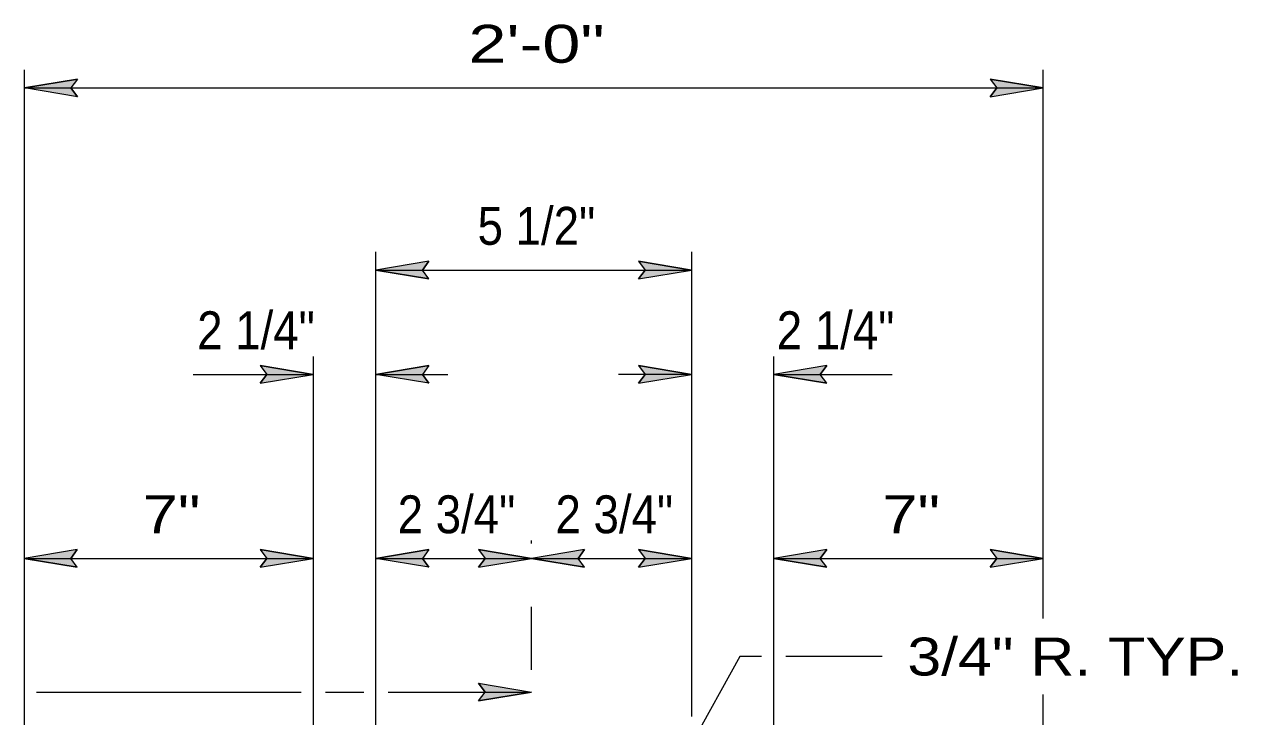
# Model space of a CAD drawing. Extents: x -9.07 to -2.08, y 8.04 to 17.77.
# Drawn here: x -6.811 to -4.889, y 16.67 to 17.766 of the extents above; entities that cross this region are included whole.
import ezdxf
from ezdxf.enums import TextEntityAlignment as Align

# ---------------------------------------------------------------- set-up
doc = ezdxf.new("R2010")
doc.units = 0
doc.header["$LTSCALE"] = 0.024
doc.linetypes.add('DOT_DASHED', pattern=[7.7, 5, -1.2, 0.3, -1.2])
doc.layers.add('10', color=7, linetype='Continuous', lineweight=13)
doc.layers.add('12', color=7, linetype='Continuous', lineweight=53)

msp = doc.modelspace()

# ---------------------------------------------------------------- hatches: boundary and pattern name
at = {"layer": '10'}
for points in [[(-6.81033, 17.665), (-6.72633, 17.679), (-6.73683, 17.665), (-6.72633, 17.651)], [(-5.19733, 17.665), (-5.28133, 17.679), (-5.27083, 17.665), (-5.28133, 17.651)], [(-6.16983, 17.39067), (-6.25383, 17.37667), (-6.16983, 17.36267), (-6.18033, 17.37667)], [(-5.754, 17.37667), (-5.838, 17.39067), (-5.8275, 17.37667), (-5.838, 17.36267)], [(-6.353, 17.2115), (-6.437, 17.2255), (-6.4265, 17.2115), (-6.437, 17.1975)], [(-6.25383, 17.2115), (-6.16983, 17.2255), (-6.18033, 17.2115), (-6.16983, 17.1975)], [(-5.754, 17.2115), (-5.838, 17.2255), (-5.8275, 17.2115), (-5.838, 17.1975)], [(-5.54, 17.2255), (-5.624, 17.2115), (-5.54, 17.1975), (-5.5505, 17.2115)], [(-6.81067, 16.92017), (-6.72667, 16.90617), (-6.73717, 16.92017), (-6.72667, 16.93417)], [(-6.437, 16.90617), (-6.353, 16.92017), (-6.437, 16.93417), (-6.4265, 16.92017)], [(-6.18033, 16.92017), (-6.16983, 16.90617), (-6.25383, 16.92017), (-6.16983, 16.93417)], [(-6.09133, 16.93417), (-6.08083, 16.92017), (-6.09133, 16.90617), (-6.00733, 16.92017)], [(-6.00733, 16.92017), (-5.92333, 16.90617), (-5.93367, 16.92017), (-5.92333, 16.93417)], [(-5.838, 16.93417), (-5.8275, 16.92017), (-5.838, 16.90617), (-5.754, 16.92017)], [(-5.54, 16.93417), (-5.624, 16.92017), (-5.54, 16.90617), (-5.5505, 16.92017)], [(-5.28133, 16.93417), (-5.27083, 16.92017), (-5.28133, 16.90617), (-5.19733, 16.92017)], [(-6.00733, 16.70867), (-6.09133, 16.69467), (-6.08083, 16.70867), (-6.09133, 16.72267)]]:
    msp.add_hatch(color=256, dxfattribs=at).paths.add_polyline_path(points)

# ---------------------------------------------------------------- linework, layer by layer
for p, q in [((-6.81067, 17.69383), (-6.81067, 14.55983)), ((-6.72633, 17.679), (-6.81033, 17.665)), ((-6.72633, 17.679), (-6.73683, 17.665)), ((-5.28133, 17.679), (-5.19733, 17.665)), ((-5.28133, 17.679), (-5.27083, 17.665)), ((-5.19733, 16.825), (-5.19733, 17.69383)), ((-6.81033, 17.665), (-5.19733, 17.665)), ((-6.72633, 17.651), (-6.81033, 17.665)), ((-6.72633, 17.651), (-6.73683, 17.665)), ((-5.28133, 17.651), (-5.19733, 17.665)), ((-5.28133, 17.651), (-5.27083, 17.665)), ((-6.16983, 17.39067), (-6.25383, 17.37667)), ((-6.16983, 17.39067), (-6.18033, 17.37667)), ((-5.838, 17.39067), (-5.754, 17.37667)), ((-5.838, 17.39067), (-5.8275, 17.37667)), ((-5.754, 17.4055), (-5.754, 16.67)), ((-6.25383, 17.37667), (-5.754, 17.37667)), ((-6.16983, 17.36267), (-6.25383, 17.37667)), ((-6.16983, 17.36267), (-6.18033, 17.37667)), ((-5.838, 17.36267), (-5.754, 17.37667)), ((-5.838, 17.36267), (-5.8275, 17.37667)), ((-5.624, 16.26517), (-5.624, 17.23967)), ((-6.437, 17.2255), (-6.353, 17.2115)), ((-6.437, 17.2255), (-6.4265, 17.2115)), ((-6.16983, 17.2255), (-6.25383, 17.2115)), ((-6.16983, 17.2255), (-6.18033, 17.2115)), ((-5.838, 17.2255), (-5.754, 17.2115)), ((-5.838, 17.2255), (-5.8275, 17.2115)), ((-5.54, 17.2255), (-5.624, 17.2115)), ((-5.54, 17.2255), (-5.5505, 17.2115)), ((-6.543, 17.2115), (-6.353, 17.2115)), ((-6.437, 17.1975), (-6.353, 17.2115)), ((-6.437, 17.1975), (-6.4265, 17.2115)), ((-6.25383, 17.2115), (-6.14017, 17.2115)), ((-6.16983, 17.1975), (-6.25383, 17.2115)), ((-6.16983, 17.1975), (-6.18033, 17.2115)), ((-5.754, 17.2115), (-5.87, 17.2115)), ((-5.838, 17.1975), (-5.754, 17.2115)), ((-5.838, 17.1975), (-5.8275, 17.2115)), ((-5.624, 17.2115), (-5.4365, 17.2115)), ((-5.54, 17.1975), (-5.624, 17.2115)), ((-5.54, 17.1975), (-5.5505, 17.2115)), ((-6.72667, 16.93417), (-6.81067, 16.92017)), ((-6.72667, 16.93417), (-6.73717, 16.92017)), ((-6.437, 16.93417), (-6.353, 16.92017)), ((-6.437, 16.93417), (-6.4265, 16.92017)), ((-6.16983, 16.93417), (-6.25383, 16.92017)), ((-6.16983, 16.93417), (-6.18033, 16.92017)), ((-6.09133, 16.93417), (-6.00733, 16.92017)), ((-6.09133, 16.93417), (-6.08083, 16.92017)), ((-5.92333, 16.93417), (-6.00733, 16.92017)), ((-5.92333, 16.93417), (-5.93367, 16.92017)), ((-5.838, 16.93417), (-5.754, 16.92017)), ((-5.838, 16.93417), (-5.8275, 16.92017)), ((-5.54, 16.93417), (-5.624, 16.92017)), ((-5.54, 16.93417), (-5.5505, 16.92017)), ((-5.28133, 16.93417), (-5.19733, 16.92017)), ((-5.28133, 16.93417), (-5.27083, 16.92017)), ((-6.72667, 16.90617), (-6.81067, 16.92017)), ((-6.81067, 16.92017), (-6.353, 16.92017)), ((-6.72667, 16.90617), (-6.73717, 16.92017)), ((-6.437, 16.90617), (-6.353, 16.92017)), ((-6.437, 16.90617), (-6.4265, 16.92017)), ((-6.25383, 16.92017), (-6.00733, 16.92017)), ((-6.16983, 16.90617), (-6.25383, 16.92017)), ((-6.16983, 16.90617), (-6.18033, 16.92017)), ((-6.09133, 16.90617), (-6.00733, 16.92017)), ((-6.09133, 16.90617), (-6.08083, 16.92017)), ((-5.92333, 16.90617), (-6.00733, 16.92017)), ((-6.00733, 16.92017), (-5.754, 16.92017)), ((-5.92333, 16.90617), (-5.93367, 16.92017)), ((-5.838, 16.90617), (-5.754, 16.92017)), ((-5.838, 16.90617), (-5.8275, 16.92017)), ((-5.624, 16.92017), (-5.19733, 16.92017)), ((-5.54, 16.90617), (-5.624, 16.92017)), ((-5.54, 16.90617), (-5.5505, 16.92017)), ((-5.28133, 16.90617), (-5.19733, 16.92017)), ((-5.28133, 16.90617), (-5.27083, 16.92017)), ((-5.67767, 16.765), (-5.77533, 16.58917)), ((-5.64317, 16.765), (-5.67767, 16.765)), ((-5.45233, 16.765), (-5.60483, 16.765)), ((-6.09133, 16.72267), (-6.00733, 16.70867)), ((-6.09133, 16.72267), (-6.08083, 16.70867)), ((-6.7915, 16.70867), (-6.37217, 16.70867)), ((-6.33367, 16.70867), (-6.27317, 16.70867)), ((-6.23467, 16.70867), (-6.00733, 16.70867)), ((-6.09133, 16.69467), (-6.00733, 16.70867)), ((-6.09133, 16.69467), (-6.08083, 16.70867)), ((-5.19733, 16.59683), (-5.19733, 16.705))]:
    msp.add_line(p, q, dxfattribs=at)
at = {"layer": '10', "linetype": 'DOT_DASHED'}
msp.add_line((-6.00733, 16.10383), (-6.00733, 16.94883), dxfattribs=at)
at = {"layer": '10'}
for points in [[(-6.81033, 17.665), (-6.72633, 17.679), (-6.73683, 17.665), (-6.72633, 17.651)], [(-5.19733, 17.665), (-5.28133, 17.679), (-5.27083, 17.665), (-5.28133, 17.651)], [(-6.16983, 17.39067), (-6.25383, 17.37667), (-6.16983, 17.36267), (-6.18033, 17.37667)], [(-5.754, 17.37667), (-5.838, 17.39067), (-5.8275, 17.37667), (-5.838, 17.36267)], [(-6.353, 17.2115), (-6.437, 17.2255), (-6.4265, 17.2115), (-6.437, 17.1975)], [(-6.25383, 17.2115), (-6.16983, 17.2255), (-6.18033, 17.2115), (-6.16983, 17.1975)], [(-5.754, 17.2115), (-5.838, 17.2255), (-5.8275, 17.2115), (-5.838, 17.1975)], [(-5.54, 17.2255), (-5.624, 17.2115), (-5.54, 17.1975), (-5.5505, 17.2115)], [(-6.81067, 16.92017), (-6.72667, 16.90617), (-6.73717, 16.92017), (-6.72667, 16.93417)], [(-6.437, 16.90617), (-6.353, 16.92017), (-6.437, 16.93417), (-6.4265, 16.92017)], [(-6.18033, 16.92017), (-6.16983, 16.90617), (-6.25383, 16.92017), (-6.16983, 16.93417)], [(-6.09133, 16.93417), (-6.08083, 16.92017), (-6.09133, 16.90617), (-6.00733, 16.92017)], [(-6.00733, 16.92017), (-5.92333, 16.90617), (-5.93367, 16.92017), (-5.92333, 16.93417)], [(-5.838, 16.93417), (-5.8275, 16.92017), (-5.838, 16.90617), (-5.754, 16.92017)], [(-5.54, 16.93417), (-5.624, 16.92017), (-5.54, 16.90617), (-5.5505, 16.92017)], [(-5.28133, 16.93417), (-5.27083, 16.92017), (-5.28133, 16.90617), (-5.19733, 16.92017)], [(-6.00733, 16.70867), (-6.09133, 16.69467), (-6.08083, 16.70867), (-6.09133, 16.72267)]]:
    msp.add_lwpolyline(points, close=True, dxfattribs=at)
for points in [[(-6.25383, 16.61317), (-6.25383, 16.707), (-6.25383, 17.4055)], [(-6.353, 17.23967), (-6.353, 16.5955), (-6.353, 15.57517)]]:
    msp.add_lwpolyline(points, dxfattribs=at)

# ---------------------------------------------------------------- texts
at = {"layer": '12'}
for s, width, p in [('2\'-0"', 1.35, (-5.9995, 17.70492)), ('5 1/2"', 0.9, (-5.99971, 17.41675)), ('2 1/4"', 0.9, (-6.44371, 17.25142)), ('2 1/4"', 0.9, (-5.52604, 17.25142)), ('7"', 1.25, (-6.5775, 16.96008)), ('2 3/4"', 0.9, (-6.12629, 16.96008)), ('2 3/4"', 0.9, (-5.87637, 16.96008)), ('7"', 1.25, (-5.40633, 16.96008))]:
    msp.add_text(s, height=0.06001, dxfattribs=dict(at, width=width)).set_placement(p, align=Align.CENTER)
at = {"layer": '12', "width": 1.2}
msp.add_text('3/4" R. TYP.', height=0.06001, dxfattribs=at).set_placement((-5.41233, 16.73492))

doc.saveas('drawing.dxf')
